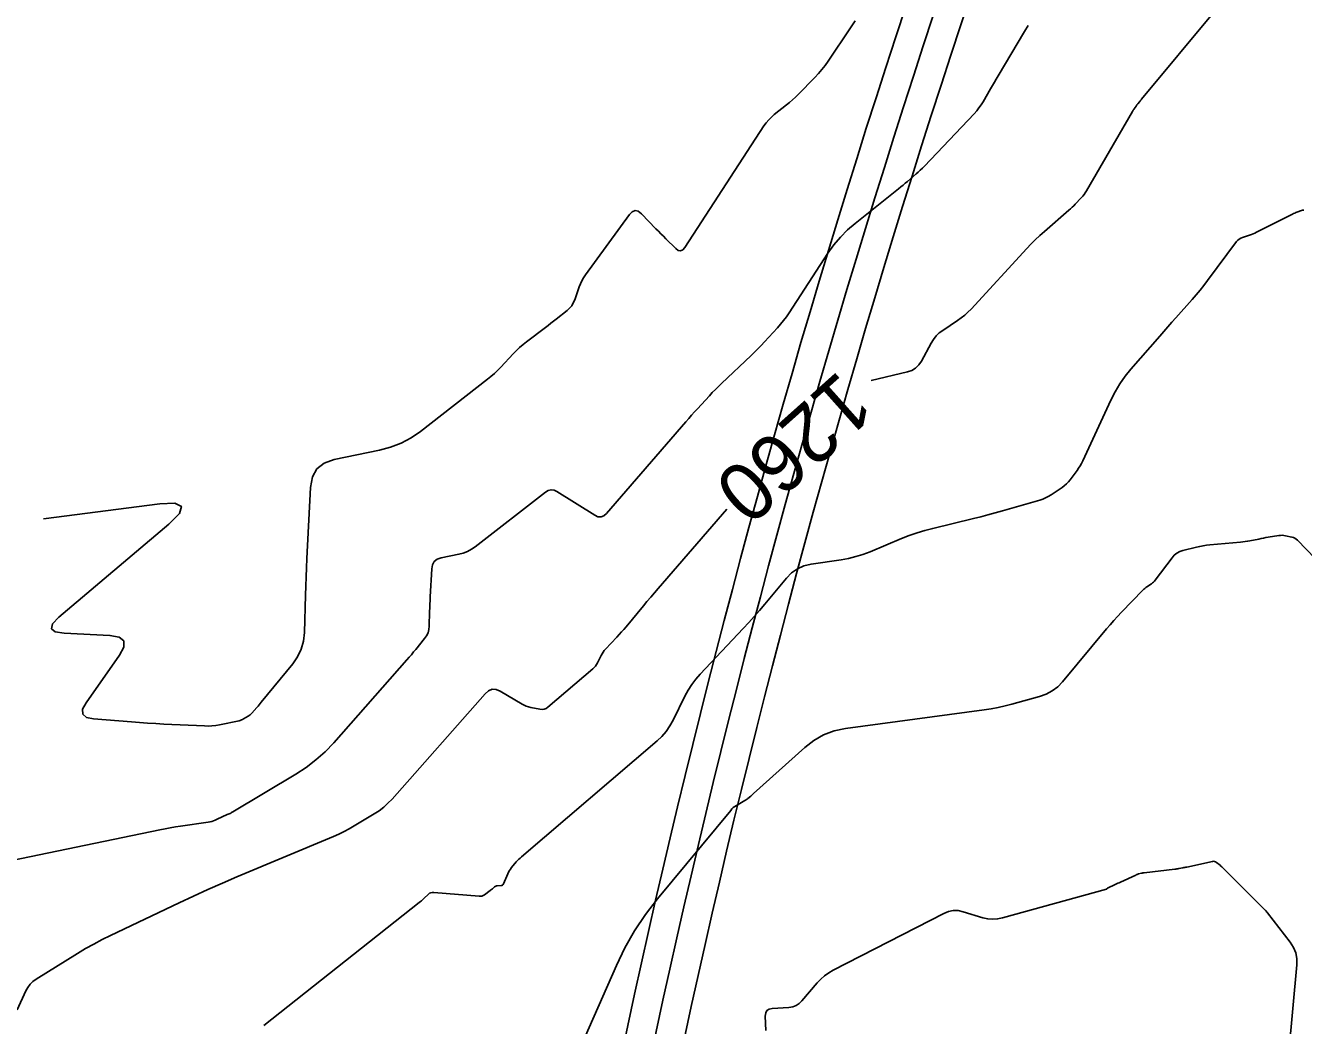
# Model space of a CAD drawing. Extents: x 658976 to 668721, y 639543 to 647196.
# Drawn here: x 661308.4 to 661440.5, y 641143.6 to 641247 of the extents above; entities that cross this region are included whole.
import ezdxf

# ---------------------------------------------------------------- set-up
doc = ezdxf.new("R2010")
doc.units = 0
for name, color, linetype in [('Ex_Contour Labels', 7, 'Continuous'), ('Ex_Major Contours', 7, 'Continuous'), ('Ex_Minor Contours', 7, 'Continuous'), ('R_Water', 7, 'Continuous')]:
    doc.layers.add(name, color=color, linetype=linetype)

msp = doc.modelspace()

# ---------------------------------------------------------------- linework, layer by layer
at = {"layer": 'Ex_Major Contours'}
for points in [[(661395.83, 641210.28), (661399.57, 641211.16), (661400.03, 641211.32), (661400.42, 641211.56), (661400.76, 641211.88), (661401.03, 641212.29), (661402.02, 641214.14), (661402.26, 641214.53), (661402.54, 641214.88), (661402.86, 641215.19), (661403.22, 641215.46), (661404.76, 641216.48), (661405.13, 641216.74), (661405.49, 641217.03), (661405.83, 641217.33), (661406.15, 641217.66), (661411.91, 641223.92), (661412.34, 641224.38), (661412.79, 641224.83), (661413.26, 641225.26), (661413.73, 641225.68), (661416.28, 641227.88), (661416.45, 641228.03), (661416.61, 641228.18), (661416.77, 641228.34), (661416.93, 641228.5), (661417.55, 641229.15), (661417.7, 641229.32), (661417.84, 641229.49), (661417.96, 641229.68), (661418.08, 641229.87), (661422.85, 641238.07), (661422.89, 641238.14), (661422.93, 641238.21), (661422.98, 641238.28), (661423.03, 641238.35), (661423.23, 641238.65), (661423.27, 641238.71), (661423.31, 641238.77), (661423.36, 641238.83), (661423.4, 641238.89), (661423.59, 641239.12), (661423.63, 641239.18), (661423.68, 641239.23), (661423.73, 641239.29), (661423.77, 641239.35), (661431.46, 641248.61)], [(661307.47, 641145.23), (661308.38, 641147.17), (661308.58, 641147.53), (661308.83, 641147.86), (661309.12, 641148.14), (661309.45, 641148.38), (661313.72, 641151.04), (661314.56, 641151.54), (661315.41, 641152.02), (661316.28, 641152.48), (661317.15, 641152.91), (661324.25, 641156.28), (661325.73, 641156.97), (661327.22, 641157.64), (661328.72, 641158.3), (661330.22, 641158.95), (661340.19, 641163.15), (661340.74, 641163.39), (661341.29, 641163.65), (661341.82, 641163.94), (661342.34, 641164.24), (661344.42, 641165.48), (661344.92, 641165.8), (661345.4, 641166.17), (661345.84, 641166.57), (661346.26, 641167), (661355.88, 641177.9), (661356.24, 641178.21), (661356.62, 641178.35), (661357.02, 641178.33), (661357.45, 641178.15), (661359.71, 641176.81), (661359.92, 641176.7), (661360.14, 641176.61), (661360.36, 641176.53), (661360.6, 641176.47), (661361.55, 641176.29), (661361.78, 641176.27), (661362, 641176.3), (661362.2, 641176.38), (661362.39, 641176.51), (661367.02, 641180.46), (661367.17, 641180.6), (661367.3, 641180.75), (661367.42, 641180.92), (661367.52, 641181.1), (661367.88, 641181.84), (661367.98, 641182.02), (661368.09, 641182.19), (661368.21, 641182.35), (661368.34, 641182.51), (661369.52, 641183.75), (661369.76, 641184.01), (661370, 641184.28), (661370.23, 641184.54), (661370.46, 641184.81), (661372.26, 641186.99), (661372.63, 641187.44), (661373.01, 641187.89), (661373.39, 641188.34), (661373.77, 641188.78), (661380.88, 641196.99)]]:
    msp.add_lwpolyline(points, dxfattribs=at)
at = {"layer": 'Ex_Minor Contours'}
for points in [[(661297.26, 641158.67), (661322.25, 641163.84), (661322.79, 641163.94), (661323.32, 641164.04), (661323.86, 641164.13), (661324.39, 641164.21), (661327.23, 641164.61), (661327.42, 641164.64), (661327.61, 641164.69), (661327.8, 641164.76), (661327.98, 641164.83), (661328.91, 641165.28), (661328.99, 641165.31), (661329.06, 641165.34), (661329.13, 641165.38), (661329.21, 641165.41), (661329.5, 641165.53), (661329.58, 641165.56), (661329.65, 641165.6), (661329.72, 641165.64), (661329.79, 641165.68), (661336.3, 641169.57), (661337.38, 641170.27), (661338.39, 641171.05), (661339.34, 641171.9), (661340.23, 641172.83), (661347.79, 641181.39), (661348.02, 641181.66), (661348.26, 641181.93), (661348.49, 641182.21), (661348.72, 641182.48), (661349.63, 641183.6), (661349.84, 641183.89), (661349.98, 641184.2), (661350.07, 641184.53), (661350.11, 641184.88), (661350.15, 641186.4), (661350.17, 641186.78), (661350.18, 641187.15), (661350.2, 641187.52), (661350.21, 641187.9), (661350.36, 641190.81), (661350.44, 641191.23), (661350.63, 641191.56), (661350.92, 641191.8), (661351.33, 641191.94), (661353.18, 641192.32), (661353.63, 641192.44), (661354.06, 641192.61), (661354.47, 641192.83), (661354.85, 641193.09), (661362.12, 641198.74), (661362.42, 641198.91), (661362.71, 641198.98), (661363.02, 641198.94), (661363.32, 641198.8), (661367.23, 641196.34), (661367.56, 641196.19), (661367.88, 641196.17), (661368.17, 641196.28), (661368.44, 641196.52), (661376.65, 641206.01), (661376.95, 641206.35), (661377.25, 641206.69), (661377.55, 641207.03), (661377.85, 641207.36), (661379.08, 641208.69), (661379.38, 641209.02), (661379.7, 641209.35), (661380.02, 641209.67), (661380.34, 641209.98), (661383.39, 641212.85), (661383.74, 641213.19), (661384.09, 641213.54), (661384.44, 641213.9), (661384.78, 641214.26), (661386.12, 641215.72), (661386.45, 641216.09), (661386.76, 641216.47), (661387.06, 641216.87), (661387.33, 641217.28), (661391.35, 641223.44), (661391.96, 641224.29), (661392.63, 641225.09), (661393.36, 641225.84), (661394.15, 641226.52), (661398.64, 641230.09), (661398.88, 641230.28), (661399.11, 641230.46), (661399.33, 641230.66), (661399.56, 641230.85), (661400.46, 641231.63), (661400.68, 641231.82), (661400.9, 641232.02), (661401.11, 641232.23), (661401.32, 641232.44), (661406.47, 641237.86), (661406.73, 641238.15), (661406.97, 641238.45), (661407.19, 641238.77), (661407.4, 641239.1), (661408.17, 641240.44), (661408.37, 641240.77), (661408.57, 641241.11), (661408.76, 641241.44), (661408.96, 641241.78), (661411.68, 641246.37), (661412.06, 641246.98)], [(661394.17, 641247.46), (661393.68, 641246.73), (661391.37, 641243.28), (661391.06, 641242.84), (661390.72, 641242.41), (661390.37, 641242), (661390, 641241.6), (661388.27, 641239.85), (661387.98, 641239.57), (661387.69, 641239.3), (661387.38, 641239.03), (661387.07, 641238.78), (661385.8, 641237.77), (661385.5, 641237.51), (661385.22, 641237.22), (661384.96, 641236.91), (661384.73, 641236.59), (661376.53, 641224.01), (661376.33, 641223.77), (661376.11, 641223.68), (661375.87, 641223.72), (661375.62, 641223.91), (661374.59, 641224.93), (661374.33, 641225.19), (661374.07, 641225.45), (661373.82, 641225.7), (661373.56, 641225.96), (661372.05, 641227.51), (661371.72, 641227.77), (661371.41, 641227.84), (661371.1, 641227.72), (661370.81, 641227.43), (661366.26, 641221.19), (661366.06, 641220.89), (661365.89, 641220.59), (661365.74, 641220.27), (661365.61, 641219.95), (661365.15, 641218.61), (661365.01, 641218.29), (661364.84, 641218), (661364.62, 641217.74), (661364.36, 641217.5), (661363.25, 641216.63), (661362.97, 641216.41), (661362.69, 641216.19), (661362.41, 641215.97), (661362.12, 641215.76), (661360.17, 641214.27), (661359.81, 641213.98), (661359.45, 641213.67), (661359.11, 641213.35), (661358.79, 641213.02), (661357.5, 641211.65), (661357.18, 641211.32), (661356.84, 641211), (661356.49, 641210.69), (661356.12, 641210.4), (661349.19, 641205.02), (661348.22, 641204.35), (661347.19, 641203.8), (661346.11, 641203.37), (661344.96, 641203.07), (661340.28, 641202.1), (661339.25, 641201.74), (661338.49, 641201.14), (661338.02, 641200.3), (661337.82, 641199.23), (661337.45, 641191.86), (661337.41, 641190.92), (661337.37, 641189.97), (661337.33, 641189.02), (661337.3, 641188.08), (661337.19, 641184.22), (661337.1, 641183.33), (661336.86, 641182.5), (661336.49, 641181.71), (661335.98, 641180.98), (661332.73, 641177.01), (661332.62, 641176.88), (661332.51, 641176.74), (661332.4, 641176.61), (661332.28, 641176.48), (661331.76, 641175.89), (661331.67, 641175.79), (661331.57, 641175.71), (661331.47, 641175.63), (661331.36, 641175.56), (661330.91, 641175.29), (661330.8, 641175.23), (661330.68, 641175.18), (661330.56, 641175.13), (661330.43, 641175.1), (661328.4, 641174.68), (661328.02, 641174.61), (661327.63, 641174.57), (661327.24, 641174.55), (661326.86, 641174.56), (661322.65, 641174.76), (661321.81, 641174.8), (661320.98, 641174.85), (661320.15, 641174.91), (661319.32, 641174.98), (661315.39, 641175.29), (661314.65, 641175.45), (661314.27, 641175.79), (661314.25, 641176.29), (661314.61, 641176.97), (661318.08, 641181.87), (661318.53, 641182.72), (661318.51, 641183.35), (661318.03, 641183.74), (661317.08, 641183.92), (661312.35, 641184.15), (661311.43, 641184.3), (661311.03, 641184.62), (661311.15, 641185.12), (661311.79, 641185.8), (661323.16, 641195.43), (661324.26, 641196.54), (661324.47, 641197.26), (661323.8, 641197.58), (661322.24, 641197.52), (661310.22, 641195.96)], [(661333.01, 641143.59), (661349.07, 641156.3), (661349.19, 641156.4), (661349.31, 641156.5), (661349.43, 641156.61), (661349.55, 641156.72), (661350.02, 641157.16), (661350.14, 641157.26), (661350.27, 641157.32), (661350.42, 641157.36), (661350.57, 641157.36), (661355.28, 641156.95), (661355.43, 641156.95), (661355.56, 641156.97), (661355.69, 641157.02), (661355.81, 641157.1), (661356.4, 641157.54), (661356.46, 641157.59), (661356.52, 641157.63), (661356.58, 641157.68), (661356.64, 641157.73), (661356.87, 641157.92), (661356.93, 641157.97), (661356.99, 641158), (661357.06, 641158.02), (661357.13, 641158.03), (661357.53, 641158.06), (661357.61, 641158.08), (661357.68, 641158.11), (661357.74, 641158.17), (661357.78, 641158.24), (661358.24, 641159.29), (661358.32, 641159.46), (661358.41, 641159.62), (661358.52, 641159.77), (661358.63, 641159.92), (661359.11, 641160.5), (661359.23, 641160.64), (661359.36, 641160.78), (661359.5, 641160.91), (661359.64, 641161.03), (661373.67, 641173.01), (661374.17, 641173.48), (661374.61, 641174), (661375, 641174.56), (661375.34, 641175.16), (661376.56, 641177.65), (661376.89, 641178.26), (661377.26, 641178.84), (661377.67, 641179.39), (661378.13, 641179.91), (661382.58, 641184.63), (661383.16, 641185.25), (661383.72, 641185.88), (661384.27, 641186.51), (661384.82, 641187.16), (661387.05, 641189.85), (661387.58, 641190.4), (661388.19, 641190.82), (661388.86, 641191.11), (661389.6, 641191.29), (661392.7, 641191.75), (661393.47, 641191.88), (661394.22, 641192.07), (661394.97, 641192.3), (661395.7, 641192.58), (661398.97, 641193.94), (661399.76, 641194.25), (661400.56, 641194.53), (661401.37, 641194.78), (661402.19, 641194.99), (661406.4, 641196), (661407.15, 641196.19), (661407.9, 641196.38), (661408.65, 641196.58), (661409.4, 641196.79), (661413.25, 641197.9), (661413.56, 641198), (661413.86, 641198.13), (661414.14, 641198.28), (661414.42, 641198.45), (661415.56, 641199.21), (661415.79, 641199.39), (661416.01, 641199.58), (661416.22, 641199.79), (661416.4, 641200.01), (661417.11, 641200.96), (661417.28, 641201.2), (661417.44, 641201.44), (661417.59, 641201.7), (661417.72, 641201.97), (661420.61, 641208.24), (661421.04, 641209.1), (661421.53, 641209.92), (661422.08, 641210.71), (661422.68, 641211.45), (661425.67, 641214.87), (661426.08, 641215.34), (661426.5, 641215.82), (661426.92, 641216.29), (661427.34, 641216.76), (661429.03, 641218.65), (661429.44, 641219.12), (661429.85, 641219.61), (661430.24, 641220.1), (661430.62, 641220.6), (661433.62, 641224.64), (661433.74, 641224.78), (661433.88, 641224.9), (661434.04, 641225), (661434.22, 641225.07), (661434.96, 641225.3), (661435.15, 641225.37), (661435.33, 641225.44), (661435.51, 641225.51), (661435.68, 641225.6), (661439.4, 641227.47), (661439.51, 641227.53), (661439.63, 641227.58), (661439.74, 641227.63), (661439.86, 641227.67), (661440.33, 641227.84), (661440.44, 641227.87), (661440.56, 641227.9)], [(661444.53, 641188.97), (661439.92, 641193.76), (661439.79, 641193.87), (661439.65, 641193.97), (661439.5, 641194.03), (661439.34, 641194.08), (661438.67, 641194.23), (661438.5, 641194.25), (661438.34, 641194.27), (661438.17, 641194.26), (661438, 641194.24), (661436.87, 641194.07), (661436.64, 641194.03), (661436.4, 641193.98), (661436.16, 641193.94), (661435.93, 641193.89), (661434.99, 641193.7), (661434.75, 641193.65), (661434.51, 641193.62), (661434.27, 641193.59), (661434.03, 641193.56), (661430.86, 641193.28), (661430.51, 641193.24), (661430.15, 641193.19), (661429.8, 641193.12), (661429.46, 641193.04), (661428.07, 641192.7), (661427.74, 641192.59), (661427.44, 641192.42), (661427.17, 641192.21), (661426.94, 641191.95), (661425.2, 641189.64), (661425.11, 641189.54), (661425.01, 641189.44), (661424.91, 641189.35), (661424.8, 641189.26), (661424.33, 641188.95), (661424.22, 641188.87), (661424.11, 641188.78), (661424.01, 641188.69), (661423.91, 641188.59), (661421.7, 641186.31), (661421.31, 641185.89), (661420.92, 641185.46), (661420.54, 641185.03), (661420.17, 641184.59), (661415.62, 641179.13), (661415.11, 641178.6), (661414.55, 641178.18), (661413.92, 641177.84), (661413.24, 641177.6), (661410.38, 641176.82), (661409.67, 641176.63), (661408.94, 641176.47), (661408.22, 641176.34), (661407.49, 641176.23), (661393.16, 641174.29), (661391.99, 641174.05), (661390.9, 641173.64), (661389.88, 641173.07), (661388.94, 641172.33), (661383.66, 641167.57), (661383.59, 641167.5), (661383.51, 641167.44), (661383.44, 641167.38), (661383.36, 641167.32), (661383.06, 641167.07), (661382.99, 641167.01), (661382.91, 641166.96), (661382.83, 641166.9), (661382.75, 641166.85), (661381.89, 641166.35), (661381.72, 641166.24), (661381.56, 641166.12), (661381.42, 641165.98), (661381.29, 641165.84), (661373.72, 641156.7), (661372.47, 641155.08), (661371.35, 641153.4), (661370.35, 641151.64), (661369.46, 641149.8), (661362.92, 641134.94)], [(661439.02, 641140.84), (661439.85, 641149.88), (661439.85, 641150.51), (661439.74, 641151.11), (661439.51, 641151.67), (661439.17, 641152.21), (661436.81, 641155.26), (661436.8, 641155.27), (661436.78, 641155.29), (661436.77, 641155.31), (661436.76, 641155.32), (661436.69, 641155.41), (661436.68, 641155.41), (661436.68, 641155.42), (661436.67, 641155.43), (661436.66, 641155.44), (661436.64, 641155.47), (661436.63, 641155.48), (661436.63, 641155.49), (661436.62, 641155.5), (661436.61, 641155.5), (661432.25, 641159.84), (661432.17, 641159.93), (661432.08, 641160.01), (661431.99, 641160.08), (661431.9, 641160.16), (661431.53, 641160.46), (661431.43, 641160.52), (661431.33, 641160.56), (661431.22, 641160.57), (661431.11, 641160.56), (661428.46, 641159.98), (661428.36, 641159.96), (661428.26, 641159.94), (661428.15, 641159.92), (661428.05, 641159.9), (661427.64, 641159.82), (661427.54, 641159.8), (661427.44, 641159.78), (661427.33, 641159.77), (661427.23, 641159.76), (661424.07, 641159.39), (661423.99, 641159.38), (661423.92, 641159.37), (661423.84, 641159.35), (661423.77, 641159.34), (661423.47, 641159.26), (661423.4, 641159.24), (661423.32, 641159.21), (661423.25, 641159.19), (661423.18, 641159.15), (661421.62, 641158.43), (661421.48, 641158.36), (661421.34, 641158.3), (661421.21, 641158.23), (661421.07, 641158.17), (661420.26, 641157.8), (661420.25, 641157.79), (661420.24, 641157.78), (661420.23, 641157.77), (661420.23, 641157.76), (661420.2, 641157.72), (661420.19, 641157.71), (661420.18, 641157.7), (661420.17, 641157.7), (661420.15, 641157.69), (661409.41, 641154.71), (661408.9, 641154.61), (661408.39, 641154.58), (661407.87, 641154.62), (661407.36, 641154.74), (661405.32, 641155.36), (661404.81, 641155.47), (661404.31, 641155.47), (661403.82, 641155.38), (661403.34, 641155.18), (661391.9, 641149.32), (661391.44, 641149.05), (661391, 641148.74), (661390.6, 641148.39), (661390.23, 641148), (661388.66, 641146.14), (661388.37, 641145.86), (661388.05, 641145.66), (661387.7, 641145.52), (661387.3, 641145.46), (661385.59, 641145.36), (661385.27, 641145.29), (661385.04, 641145.14), (661384.91, 641144.9), (661384.87, 641144.57), (661384.93, 641143.07)]]:
    msp.add_lwpolyline(points, dxfattribs=at)
at = {"layer": 'R_Water'}
for radius in [1015.93, 1012.93, 1009.93]:
    msp.add_arc((662363.66, 640929.07), radius, 156.60619, 168.55644, dxfattribs=at)

# ---------------------------------------------------------------- texts
at = {"layer": 'Ex_Contour Labels'}
msp.add_text('1260', height=6, rotation=221.7552, dxfattribs=at).set_placement((661392.55, 641211.45))

doc.saveas('drawing.dxf')
